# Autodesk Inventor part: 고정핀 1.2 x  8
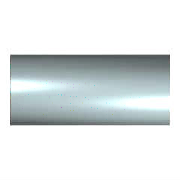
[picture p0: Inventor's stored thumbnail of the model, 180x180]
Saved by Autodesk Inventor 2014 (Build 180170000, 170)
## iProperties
IsCustomPart: 1
Created: 2012-02
Part Number: 고정핀 1.2 x  8
Material: 강철, 연강
Description: 평행 핀
Document SubType Name: Modeling
Standard: KS B 1320
Designer: P15F
Standards Organization: KS
Language: ko-KR
Size Designation: C 1.2 x  8
Categories: <MemberInstance><Categories><Category DisplayName="조임쇠" InternalName="e4da775c-781d-43d5-af7c-5136215cf5a6" Mnemonic="FSTN"><Category DisplayName="핀" InternalNa
Density: 1 g/cm^3
Appearance: 노란색
Author: P15F
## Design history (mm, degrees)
sketch "스케치1"
  geometry: C1 r 0.6 at (0, 0); 1 further point
  constraints: 1 centre point, 1 coincident
  dimensions: "d1" = 1.2 diameter of C1 (= NND)
extrude "본체" new body sketch "스케치1" distance "d2" = 8 (= NLG); taper "d3" = 0 deg
node "작업 평면1"
body "Solid1"
other parameters: "NND" = 1.2 [user parameter; used in 1 equation term], "NLG" = 8 [user parameter; used in 1 equation term], "d8" = 0, "d9" = 0, "d10" = 0
